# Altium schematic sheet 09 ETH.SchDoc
size 420 x 297 mm
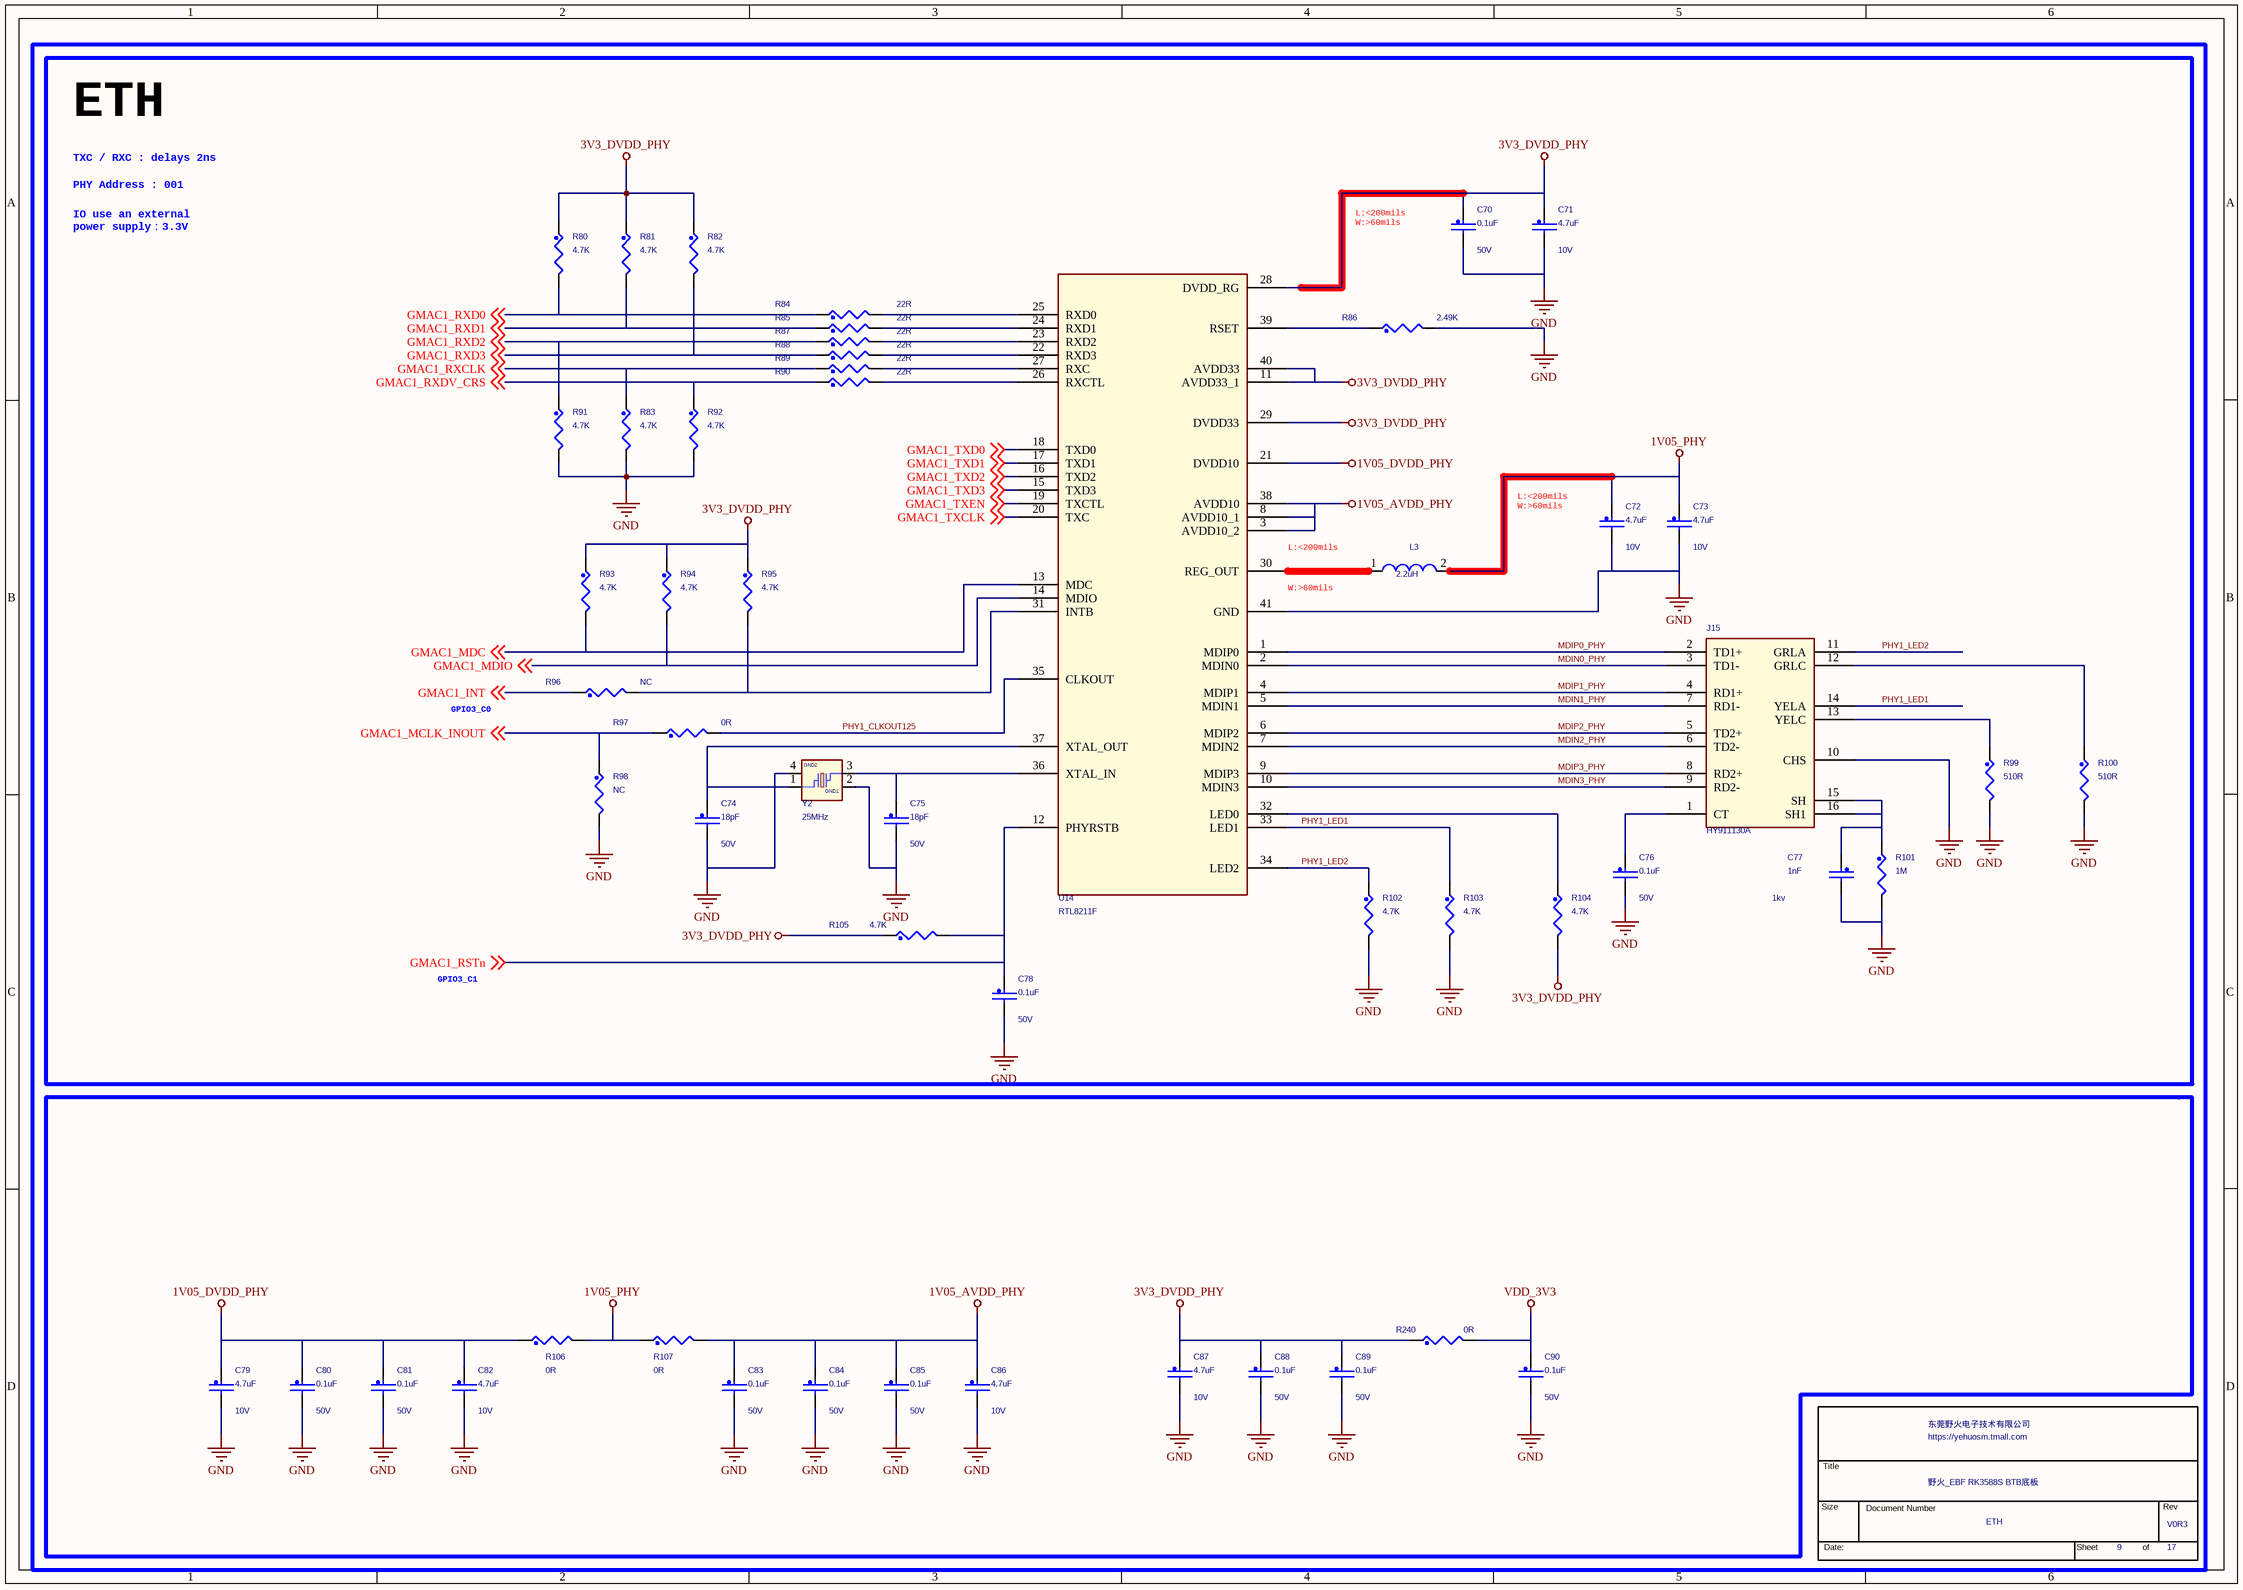
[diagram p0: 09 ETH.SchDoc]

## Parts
*  Page Count: 17  Page Number: 9  OrgName: 东莞野火电子技术有限公司  Title: 野火_EBF RK3588S BTB底板  RevCode: V0R3  Doc: ETH  (hidden comment: TitleBlock_YHSCH)  (graphical)
C70  0.1uF  Voltage: 50V  [C0402]
C71  4.7uF  Voltage: 10V  [C0402]
C72  4.7uF  Voltage: 10V  [C0402]
C73  4.7uF  Voltage: 10V  [C0402]
C74  18pF  Voltage: 50V  [C0402]
C75  18pF  Voltage: 50V  [C0402]
C76  0.1uF  Voltage: 50V  [C0402]
C77  1nF  Voltage: 1kv  [C0805]
C78  0.1uF  Voltage: 50V  [C0402]
C79  4.7uF  Voltage: 10V  [C0402]
C80  0.1uF  Voltage: 50V  [C0402]
C81  0.1uF  Voltage: 50V  [C0402]
C82  4.7uF  Voltage: 10V  [C0402]
C83  0.1uF  Voltage: 50V  [C0402]
C84  0.1uF  Voltage: 50V  [C0402]
C85  0.1uF  Voltage: 50V  [C0402]
C86  4.7uF  Voltage: 10V  [C0402]
C87  4.7uF  Voltage: 10V  [C0402]
C88  0.1uF  Voltage: 50V  [C0402]
C89  0.1uF  Voltage: 50V  [C0402]
C90  0.1uF  Voltage: 50V  [C0402]
J15  HY911130A  [HY911130A]
L3  2.2uH  [L2520]
R80  4.7K  [R0402]
R81  4.7K  [R0402]
R82  4.7K  [R0402]
R83  4.7K  [R0402]
R84  22R  [R0402]
R85  22R  [R0402]
R86  2.49K  [R0402]
R87  22R  [R0402]
R88  22R  [R0402]
R89  22R  [R0402]
R90  22R  [R0402]
R91  4.7K  [R0402]
R92  4.7K  [R0402]
R93  4.7K  [R0402]
R94  4.7K  [R0402]
R95  4.7K  [R0402]
R96  NC  [R0402]
R97  0R  [R0402]
R98  NC  [R0402]
R99  510R  [R0402]
R100  510R  [R0402]
R101  1M  [R0805]
R102  4.7K  [R0402]
R103  4.7K  [R0402]
R104  4.7K  [R0402]
R105  4.7K  [R0402]
R106  0R  [R0402]
R107  0R  [R0402]
R240  0R  [R0402]
U14  RTL8211F  [qfp_40p_r]
Y2  25MHz  [3225]

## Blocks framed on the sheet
ETH: C70-C78 J15 L3 R80-R105 U14 Y2

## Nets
1V05_AVDD_PHY: C83.1 C84.1 C85.1 C86.1 R107.2 U14.3(AVDD10_2) U14.8(AVDD10_1) U14.38(AVDD10)
1V05_DVDD_PHY: C79.1 C80.1 C81.1 C82.1 R106.1 U14.21(DVDD10)
1V05_PHY: C72.1 C73.1 L3.2 R106.2 R107.1
3V3_DVDD_PHY: C70.1 C71.1 C87.1 C88.1 C89.1 R80.1 R81.1 R82.1 R93.1 R94.1 R95.1 R104.2 R105.1 R240.1 U14.11(AVDD33_1) U14.28(DVDD_RG) U14.29(DVDD33) U14.40(AVDD33)
GND: C70.2 C71.2 C72.2 C73.2 C74.2 C75.2 C76.2 C77.2 C78.2 C79.2 C80.2 C81.2 C82.2 C83.2 C84.2 C85.2 C86.2 C87.2 C88.2 C89.2 C90.2 J15.10(CHS) R83.2 R86.2 R91.2 R92.2 R98.2 R99.2 R100.2 R101.2 R102.2 R103.2 U14.41(GND) Y2.2(GND1) Y2.4(GND2)
VDD_3V3: C90.1 R240.2
GMAC1_INT: R96.1 ; off-sheet GMAC1_INT
GMAC1_MCLK_INOUT: R97.1 R98.1 ; off-sheet GMAC1_MCLK_INOUT
GMAC1_MDC: R93.2 U14.13(MDC) ; off-sheet GMAC1_MDC
GMAC1_MDIO: R94.2 U14.14(MDIO) ; off-sheet GMAC1_MDIO
GMAC1_RSTn: C78.1 R105.2 U14.12(PHYRSTB) ; off-sheet GMAC1_RSTn
GMAC1_RXCLK: R83.1 R89.1 ; off-sheet GMAC1_RXCLK
GMAC1_RXD0: R80.2 R84.1 ; off-sheet GMAC1_RXD0
GMAC1_RXD1: R81.2 R85.1 ; off-sheet GMAC1_RXD1
GMAC1_RXD2: R87.1 R91.1 ; off-sheet GMAC1_RXD2
GMAC1_RXD3: R82.2 R88.1 ; off-sheet GMAC1_RXD3
GMAC1_RXDV_CRS: R90.1 R92.1 ; off-sheet GMAC1_RXDV_CRS
GMAC1_TXCLK: U14.20(TXC) ; off-sheet GMAC1_TXCLK
GMAC1_TXD0: U14.18(TXD0) ; off-sheet GMAC1_TXD0
GMAC1_TXD1: U14.17(TXD1) ; off-sheet GMAC1_TXD1
GMAC1_TXD2: U14.16(TXD2) ; off-sheet GMAC1_TXD2
GMAC1_TXD3: U14.15(TXD3) ; off-sheet GMAC1_TXD3
GMAC1_TXEN: U14.19(TXCTL) ; off-sheet GMAC1_TXEN
MDIN0_PHY: J15.3(TD1-) U14.2(MDIN0)
MDIN1_PHY: J15.7(RD1-) U14.5(MDIN1)
MDIN2_PHY: J15.6(TD2-) U14.7(MDIN2)
MDIN3_PHY: J15.9(RD2-) U14.10(MDIN3)
MDIP0_PHY: J15.2(TD1+) U14.1(MDIP0)
MDIP1_PHY: J15.4(RD1+) U14.4(MDIP1)
MDIP2_PHY: J15.5(TD2+) U14.6(MDIP2)
MDIP3_PHY: J15.8(RD2+) U14.9(MDIP3)
PHY1_CLKOUT125: R97.2 U14.35(CLKOUT)
PHY1_LED1: J15.14(YELA) R103.1 U14.33(LED1)
PHY1_LED2: J15.11(GRLA) R102.1 U14.34(LED2)
NetC74_1: C74.1 U14.37(XTAL_OUT) Y2.1
NetC75_1: C75.1 U14.36(XTAL_IN) Y2.3
NetC76_1: C76.1 J15.1(CT)
NetC77_1: C77.1 J15.15(SH) J15.16(SH1) R101.1
NetJ15_12: J15.12(GRLC) R100.1
NetJ15_13: J15.13(YELC) R99.1
NetL3_1: L3.1 U14.30(REG_OUT)
NetR84_2: R84.2 U14.25(RXD0)
NetR85_2: R85.2 U14.24(RXD1)
NetR86_1: R86.1 U14.39(RSET)
NetR87_2: R87.2 U14.23(RXD2)
NetR88_2: R88.2 U14.22(RXD3)
NetR89_2: R89.2 U14.27(RXC)
NetR90_2: R90.2 U14.26(RXCTL)
NetR95_2: R95.2 R96.2 U14.31(INTB)
NetR104_1: R104.1 U14.32(LED0)

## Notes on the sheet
- PHY Address : 001
- TXC / RXC : delays 2ns
- IO use an external
  power supply：3.3V
- (near C70) L:<200mils
  W:>60mils
- (near C72) L:<200mils
  W:>60mils
- L:<200mils
- W:>60mils
- GPIO3_C0
- GPIO3_C1

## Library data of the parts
* = TitleBlock_YHSCH: Cage Code: 1
C70 C78 C81 C84 C89 = CAP_NP: CLASS: DISCRETE; 生命周期: 量产; 价格: 0.029826; 规格书: 风华电容.pdf; 类别: 贴片电容0402; 品牌: 风华; 条码: EBF29060118; 规格编号: 0402X104K500NT; 规格: 贴片电容0.1uF 10% 50V X5R 0402
C71 C73 C79 C86 C87 = CAP_NP: CLASS: DISCRETE; 规格: 贴片电容4.7uF 10% 10V X5R 0402; 规格编号: CC0402KRX5R6BB475; 条码: EBF29060248; 品牌: 国巨; 类别: 贴片电容0402; 规格书: 国巨-贴片电容.pdf; 价格: 0.059058; 生命周期: 量产
C72 C82 = CAP_NP: CLASS: DISCRETE; 生命周期: 量产; 价格: 0.059058; 规格书: 国巨-贴片电容.pdf; 类别: 贴片电容0402; 品牌: 国巨; 条码: EBF29060248; 规格编号: CC0402KRX5R6BB475; 规格: 贴片电容4.7uF 10% 10V X5R 0402
C74 C75 = CAP_NP: CLASS: DISCRETE; 规格: 贴片电容18pF 5% 50V C0G 0402; 规格编号: 0402CG180J500NT; 条码: EBF29060235; 品牌: 风华; 类别: 贴片电容0402; 规格书: 风华电容.pdf; 价格: 0.00515; 生命周期: 量产
C76 C80 C83 C85 C88 C90 = CAP_NP: CLASS: DISCRETE; 规格: 贴片电容0.1uF 10% 50V X5R 0402; 规格编号: 0402X104K500NT; 条码: EBF29060118; 品牌: 风华; 类别: 贴片电容0402; 规格书: 风华电容.pdf; 价格: 0.029826; 生命周期: 量产
C77 = CAP_NP: CLASS: DISCRETE; 规格: 贴片电容1nF 10% 1kV X7R 0805; 规格编号: 0805B102K102CT; 条码: EBF29060304; 品牌: 华新科; 类别: 贴片电容0805; 规格书: 华新科0805系列高压贴片电容.pdf; 价格: 0.083527; 生命周期: 量产
J15 = HY911130A: 规格: 屏蔽式以太网连接器RJ45 引脚数14 LED灯黄绿 1000M; 条码: EBF29040053; 品牌: 汉仁; 类别: 网口; 规格书: 汉仁_1000M_ HY911130A.pdf; 价格: 11.12; 生命周期: 量产
L3 = IND: CLASS: DISCRETE; 生命周期: 量产; 价格: 0.129914; 规格书: 佳邦_ WIP252012P-2R2ML.pdf; 类别: 贴片电感2520; 品牌: 佳邦; 条码: EBFCIS220927171910; 规格编号: WIP252012P-2R2ML; 规格: 功率电感2.2uH 2.2uH ±20% 2.06A 85mΩ
R80 R92-R95 R104 = RES: CLASS: DISCRETE; 规格: 贴片电阻4.7K 1% 1/16W 0402; 规格编号: RI0402L4701FT; 条码: EBF29070047; 品牌: 合科泰; 类别: 贴片电阻0402; 规格书: 合科泰-RI系列电阻.pdf; 生命周期: 量产
R81-R83 R91 R102 R103 = RES: CLASS: DISCRETE; 生命周期: 量产; 规格书: 合科泰-RI系列电阻.pdf; 类别: 贴片电阻0402; 品牌: 合科泰; 条码: EBF29070047; 规格编号: RI0402L4701FT; 规格: 贴片电阻4.7K 1% 1/16W 0402
R84 R85 R87-R90 = RES: CLASS: DISCRETE; 生命周期: 量产; 规格书: 合科泰-RI系列电阻.pdf; 类别: 贴片电阻0402; 品牌: 合科泰; 条码: EBF29070181; 规格编号: RI0402L22R0FT; 规格: 贴片电阻22R 1% 1/16W 0402
R86 = RES: CLASS: DISCRETE; 规格: 贴片电阻2.49K 1% 1/16W 0402; 规格编号: 0402WGF2491TCE; 条码: EBF29070292; 品牌: 厚声; 类别: 贴片电阻0402; 规格书: 厚声-无铅厚膜电阻.pdf; 生命周期: 量产; 价格: 0.004709
R96 R98 = RES: CLASS: DISCRETE; 类别: 贴片电阻0402; 条码: EBF29070087; 规格: 贴片电阻NC 预留
R97 R106 R107 = RES: CLASS: DISCRETE; 规格: 贴片电阻0R 1% 1/16W 0402; 规格编号: RI0402L000FT; 条码: EBF29070049; 品牌: 合科泰; 类别: 贴片电阻0402; 规格书: 合科泰-RI系列电阻.pdf; 生命周期: 量产
R99 = RES: CLASS: DISCRETE; 生命周期: 量产; 规格书: 厚声-无铅厚膜电阻.pdf; 类别: 贴片电阻0402; 品牌: 厚声; 条码: EBF29070293; 规格编号: 0402WGF5100TCE; 规格: 贴片电阻510R 1% 1/16W 0402; 价格: 0.003791
R100 = RES: CLASS: DISCRETE; 价格: 0.003791; 规格: 贴片电阻510R 1% 1/16W 0402; 规格编号: 0402WGF5100TCE; 条码: EBF29070293; 品牌: 厚声; 类别: 贴片电阻0402; 规格书: 厚声-无铅厚膜电阻.pdf; 生命周期: 量产
R101 = RES: CLASS: DISCRETE; 规格: 贴片电阻1M 1% 1/8W 0805; 规格编号: AC0805FR-071ML; 条码: EBF29070294; 品牌: 国巨; 类别: 贴片电阻0805; 规格书: YAGEO国巨厚膜无铅电阻.pdf; 价格: 0.02396; 生命周期: 量产
R105 = RES: CLASS: DISCRETE; 生命周期: 量产; 规格书: 合科泰-RI系列电阻.pdf; 品牌: 合科泰; 规格编号: RI0402L4701FT; 类别: 贴片电阻0402; 条码: EBF29070047; 规格: 贴片电阻4.7K 1% 1/16W 0402
R240 = RES: CLASS: DISCRETE; 生命周期: 量产; 规格书: 合科泰-RI系列电阻.pdf; 类别: 贴片电阻0402; 品牌: 合科泰; 条码: EBF29070049; 规格编号: RI0402L000FT; 规格: 贴片电阻0R 1% 1/16W 0402
U14 = RTL8211F: 生命周期: 量产; 规格书: 瑞昱_RTL8211F-CG.pdf; 类别: 以太网芯片; 品牌: 瑞昱; 条码: EBF29150018; 规格编号: RTL8211F-CG; 规格: 以太网芯片 10M/100M/1000M 控制接口：RGMII RGMII电压：3.3V/2.5V/1.8V/1.5V; 价格: 15.2
Y2 = CRYSTAL_4P: CLASS: IC; 生命周期: 量产; 价格: 0.385846; 规格书: 扬兴科技-25MHZ.pdf; 类别: 贴片晶振 3225; 品牌: 扬兴科技; 条码: EBF29100005; 规格编号: X322525MQB4SI; 规格: 无源晶振25MHz ±10ppm 50Ω 16pF -40℃~+85℃ 3225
